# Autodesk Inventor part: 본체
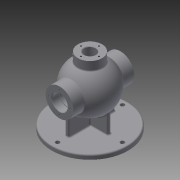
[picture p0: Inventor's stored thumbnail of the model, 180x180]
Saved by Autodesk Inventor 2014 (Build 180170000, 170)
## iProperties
Created: 2020-08
Part Number: 본체
Material: Generic
Document SubType Name: Modeling
Designer: kh
Density: 1 g/cm^3
Appearance: Default
Author: kh
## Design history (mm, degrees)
sketch "Sketch1"
  geometry: C1 r 85 at (0, 0); 1 further point
  constraints: 1 centre point, 1 coincident
  dimensions: "d0" = 170 diameter of C1
extrude "Extrusion1" new body sketch "Sketch1" distance "d1" = 10; taper "d2" = 0 deg
sketch "Sketch2"
  geometry: L1 (-68, 85)-(68, 85); A1 r 53 centre (0, 85) between (53, 85) and (-53, 85); 2 further points
  constraints: 2 end point, 2 point on circle, 2 point on line, 1 centre point, 1 coincident, 1 horizontal, 1 midpoint, 1 vertical alignment
  dimensions: "d3" = 136 distance of L1.start L1.end; "d4" = 85 distance from line of point (0, 0) L1; "d5" = 106 diameter of A1
revolve "Revolution1" sketch "Sketch2" stored, may be unused: angle "d6" = 90 deg
sketch "Sketch4"
  geometry: L1 (-68, 85)-(68, 85); L2 (-68, 102.5)-(-68, 116); L3 (-68, 116)-(-42.988, 116); L4 (-68, 102.5)-(-50.027, 102.5); L5 (-50.027, 102.5)-(-42.988, 102.5); L6 (-42.988, 116)-(-42.988, 102.5); A1 r 53 centre (0, 85) between (-42.988, 116) and (-50.027, 102.5) reference; 2 further points
  constraints: 12 end point, 3 perpendicular, 2 point on circle, 1 coincident, 1 collinear, 1 horizontal, 1 midpoint, 1 parallel, 1 vertical alignment
  dimensions: "d7" = 85 distance from line of point (0, 0) L1; "d8" = 136 distance of L1.start L1.end; "d9" = 35 diameter of L2.start L1; "d10" = 62 diameter of L2.end L1
revolve "Revolution2" sketch "Sketch4" stored, may be unused: angle "d11" = 90 deg
mirror "Mirror1"
sketch "Sketch5"
  geometry: L1 (43, 85)-(-43, 85); A1 r 53 centre (0, 85) between (42.988, 116) and (42.988, 54) reference; A2 r 53 centre (0, 85) between (50.027, 67.5) and (50.027, 102.5) reference; A3 r 53 centre (0, 85) between (50.027, 102.5) and (42.988, 116); A4 r 53 centre (0, 85) between (42.988, 54) and (50.027, 67.5); A5 r 43 centre (0, 85) between (-43, 85) and (43, 85); 1 further point
  constraints: 6 point on circle, 3 centre point, 3 coincident, 2 end point, 1 horizontal, 1 midpoint
  dimensions: "d12" = 86 diameter of A5
revolve "Revolution3" sketch "Sketch5" stored, may be unused: angle "d13" = 90 deg
workplane "Work Plane1"
sketch "Sketch7"
  geometry: C1 r 17.5 at (0, 0) reference; C2 r 17.5 at (0, 0); 1 further point
  constraints: 1 centre point, 1 coincident, 1 concentric
extrude "Extrusion2" cut sketch "Sketch7" stored distance "d15" = 10; taper "d16" = 0 deg
workplane "Work Plane2"
sketch "Sketch8"
  geometry: C1 r 27 at (0, 0); 1 further point
  constraints: 1 centre point, 1 coincident
  dimensions: "d18" = 54 diameter of C1
extrude "Extrusion3" join sketch "Sketch8" stored distance "d19" = 10; taper "d20" = 0 deg
sketch "Sketch9"
  geometry: C1 r 13 at (0, 0); 1 further point
  constraints: 1 centre point, 1 coincident
  dimensions: "d21" = 26 diameter of C1
extrude "Extrusion4" cut sketch "Sketch9" stored distance "d22" = 10; taper "d23" = 0 deg
sketch "Sketch10"
  geometry: 2 further points
  constraints: 1 vertical alignment
  dimensions: "d24" = 20 distance of point (0, 0) point (0, 20)
hole "Hole1" sketch "Sketch10" at (0, 20) diameter "d25" = 3.459; stored, may be unused: countersink angle "d29" = 90 deg, drill point angle "d31" = 118 deg; dims "d26" = 12, "d27" = 4, "d28" = 2, "d30" = 15
pattern_circular "Circular Pattern1" dims angle "d33" = 360 deg
sketch "Sketch11" dims "d35" = 48
  geometry: C1 r 31 at (0, 0) reference; 3 further points
  constraints: 2 vertical alignment, 1 coincident, 2 other
hole "Hole2" sketch "Sketch11" at (0, 24) diameter "d36" = 3.459; stored, may be unused: countersink angle "d40" = 90 deg, drill point angle "d42" = 118 deg; dims "d37" = 12, "d38" = 4, "d39" = 2, "d41" = 15
pattern_circular "Circular Pattern2" dims angle "d44" = 360 deg
mirror "Mirror2"
sketch "Sketch12"
  geometry: L1 (-4, -52)-(4, -52); L2 (4, -52)-(4, 52); L3 (4, 52)-(-4, 52); L4 (-4, 52)-(-4, -52); L5 (-4, -52)-(4, 52); L6 (4, -52)-(-4, 52); L7 (-43, -4)-(43, -4); L8 (43, -4)-(43, 4); L9 (43, 4)-(-43, 4); L10 (-43, 4)-(-43, -4); L11 (-43, -4)-(43, 4); L12 (43, -4)-(-43, 4); 1 further point
  constraints: 24 end point, 4 midpoint, 4 parallel, 2 horizontal, 2 perpendicular
  dimensions: "d47" = 8 distance of L3.end L2.end; "d48" = 104 distance of L2.end L1.end; "d49" = 86 distance of L9.end L8.end; "d50" = 8 distance of L8.end L7.end
extrude "Extrusion5" join sketch "Sketch12" stored distance "d51" = 10; taper "d52" = 0 deg
chamfer "Chamfer1" distance "d53" = 1; stored, may be unused: second distance "d54" = 2, angle "d55" = 45 deg
chamfer "Chamfer2" distance "d56" = 1; stored, may be unused: second distance "d57" = 2, angle "d58" = 45 deg
chamfer "Chamfer3" distance "d59" = 1; stored, may be unused: second distance "d60" = 2, angle "d61" = 45 deg
sketch "Sketch13"
  geometry: L1 (0, 85)-(-80.895, 85); L2 (-52, 85)-(-52, 103.5); L3 (-52, 103.5)-(-50.25, 103.5); L4 (-50.25, 103.5)-(-50.25, 85); L5 (-68, 103.5)-(-68, 66.5) reference; A1 r 43 centre (0, 85) between (-39.278, 67.5) and (-39.278, 102.5) reference; 1 further point
  constraints: 8 end point, 2 perpendicular, 2 point on line, 1 horizontal, 1 parallel
  dimensions: "d62" = 1.75 distance of L2.end L3.end; "d63" = 16 distance between parallel lines of L5 L2; "d64" = 37 diameter of L3 L1
revolve "Revolution4" sketch "Sketch13" stored, may be unused: angle "d65" = 90 deg
sketch "Sketch14" dims "d66" = 145
  geometry: C1 r 4.5 at (0, 72.5); 2 further points
  constraints: 2 vertical alignment, 1 centre point, 1 coincident, 2 other
  dimensions: "d67" = 9 diameter of C1
extrude "Extrusion6" cut sketch "Sketch14" stored distance "d68" = 10; taper "d69" = 0 deg
pattern_circular "Circular Pattern3" dims angle "d71" = 360 deg
fillet "Fillet1" dims "d73" = 3
fillet "Fillet2" dims "d74" = 3
fillet "Fillet3" dims "d75" = 3
fillet "Fillet4" dims "d76" = 3
workplane "Work Plane3"
sketch "Sketch15"
  geometry: L1 (-14.532, -3.954)-(14.532, -3.954); L2 (14.532, -3.954)-(14.532, -14.046); L3 (14.532, -14.046)-(-14.532, -14.046); L4 (-14.532, -14.046)-(-14.532, -3.954); L5 (-14.532, -14.046)-(14.532, -3.954); L6 (-27, 0)-(27, 0) reference; L7 (-27, 0)-(-27, -19.393) reference; 2 further points
  constraints: 2 end point, 1 midpoint, 2 other
  dimensions: "d77" = 27 horizontal distance of L6.start point (0, -9); "d78" = 9 vertical distance of point (0, -9) L6.start
emboss "Emboss1" sketch "Sketch15" dims "d79" = 0.5, "d80" = 0
fillet "Fillet5" dims "d81" = 3
body "Solid1"
other parameters: "d14" = 0
